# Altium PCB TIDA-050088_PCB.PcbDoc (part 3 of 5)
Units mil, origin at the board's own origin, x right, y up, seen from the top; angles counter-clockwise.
Board outline 8500 x 7000 mil, 8 copper layers (Top Layer, Layer 1 - GND, Signal Layer 2, Layer 3 - GND, Layer 4 - Power, Signal Layer 5, Layer 6 - GND, Bottom Layer), stack 61.6 mil thick; 537 components, 169 nets, 1427 pads, 1411 vias.
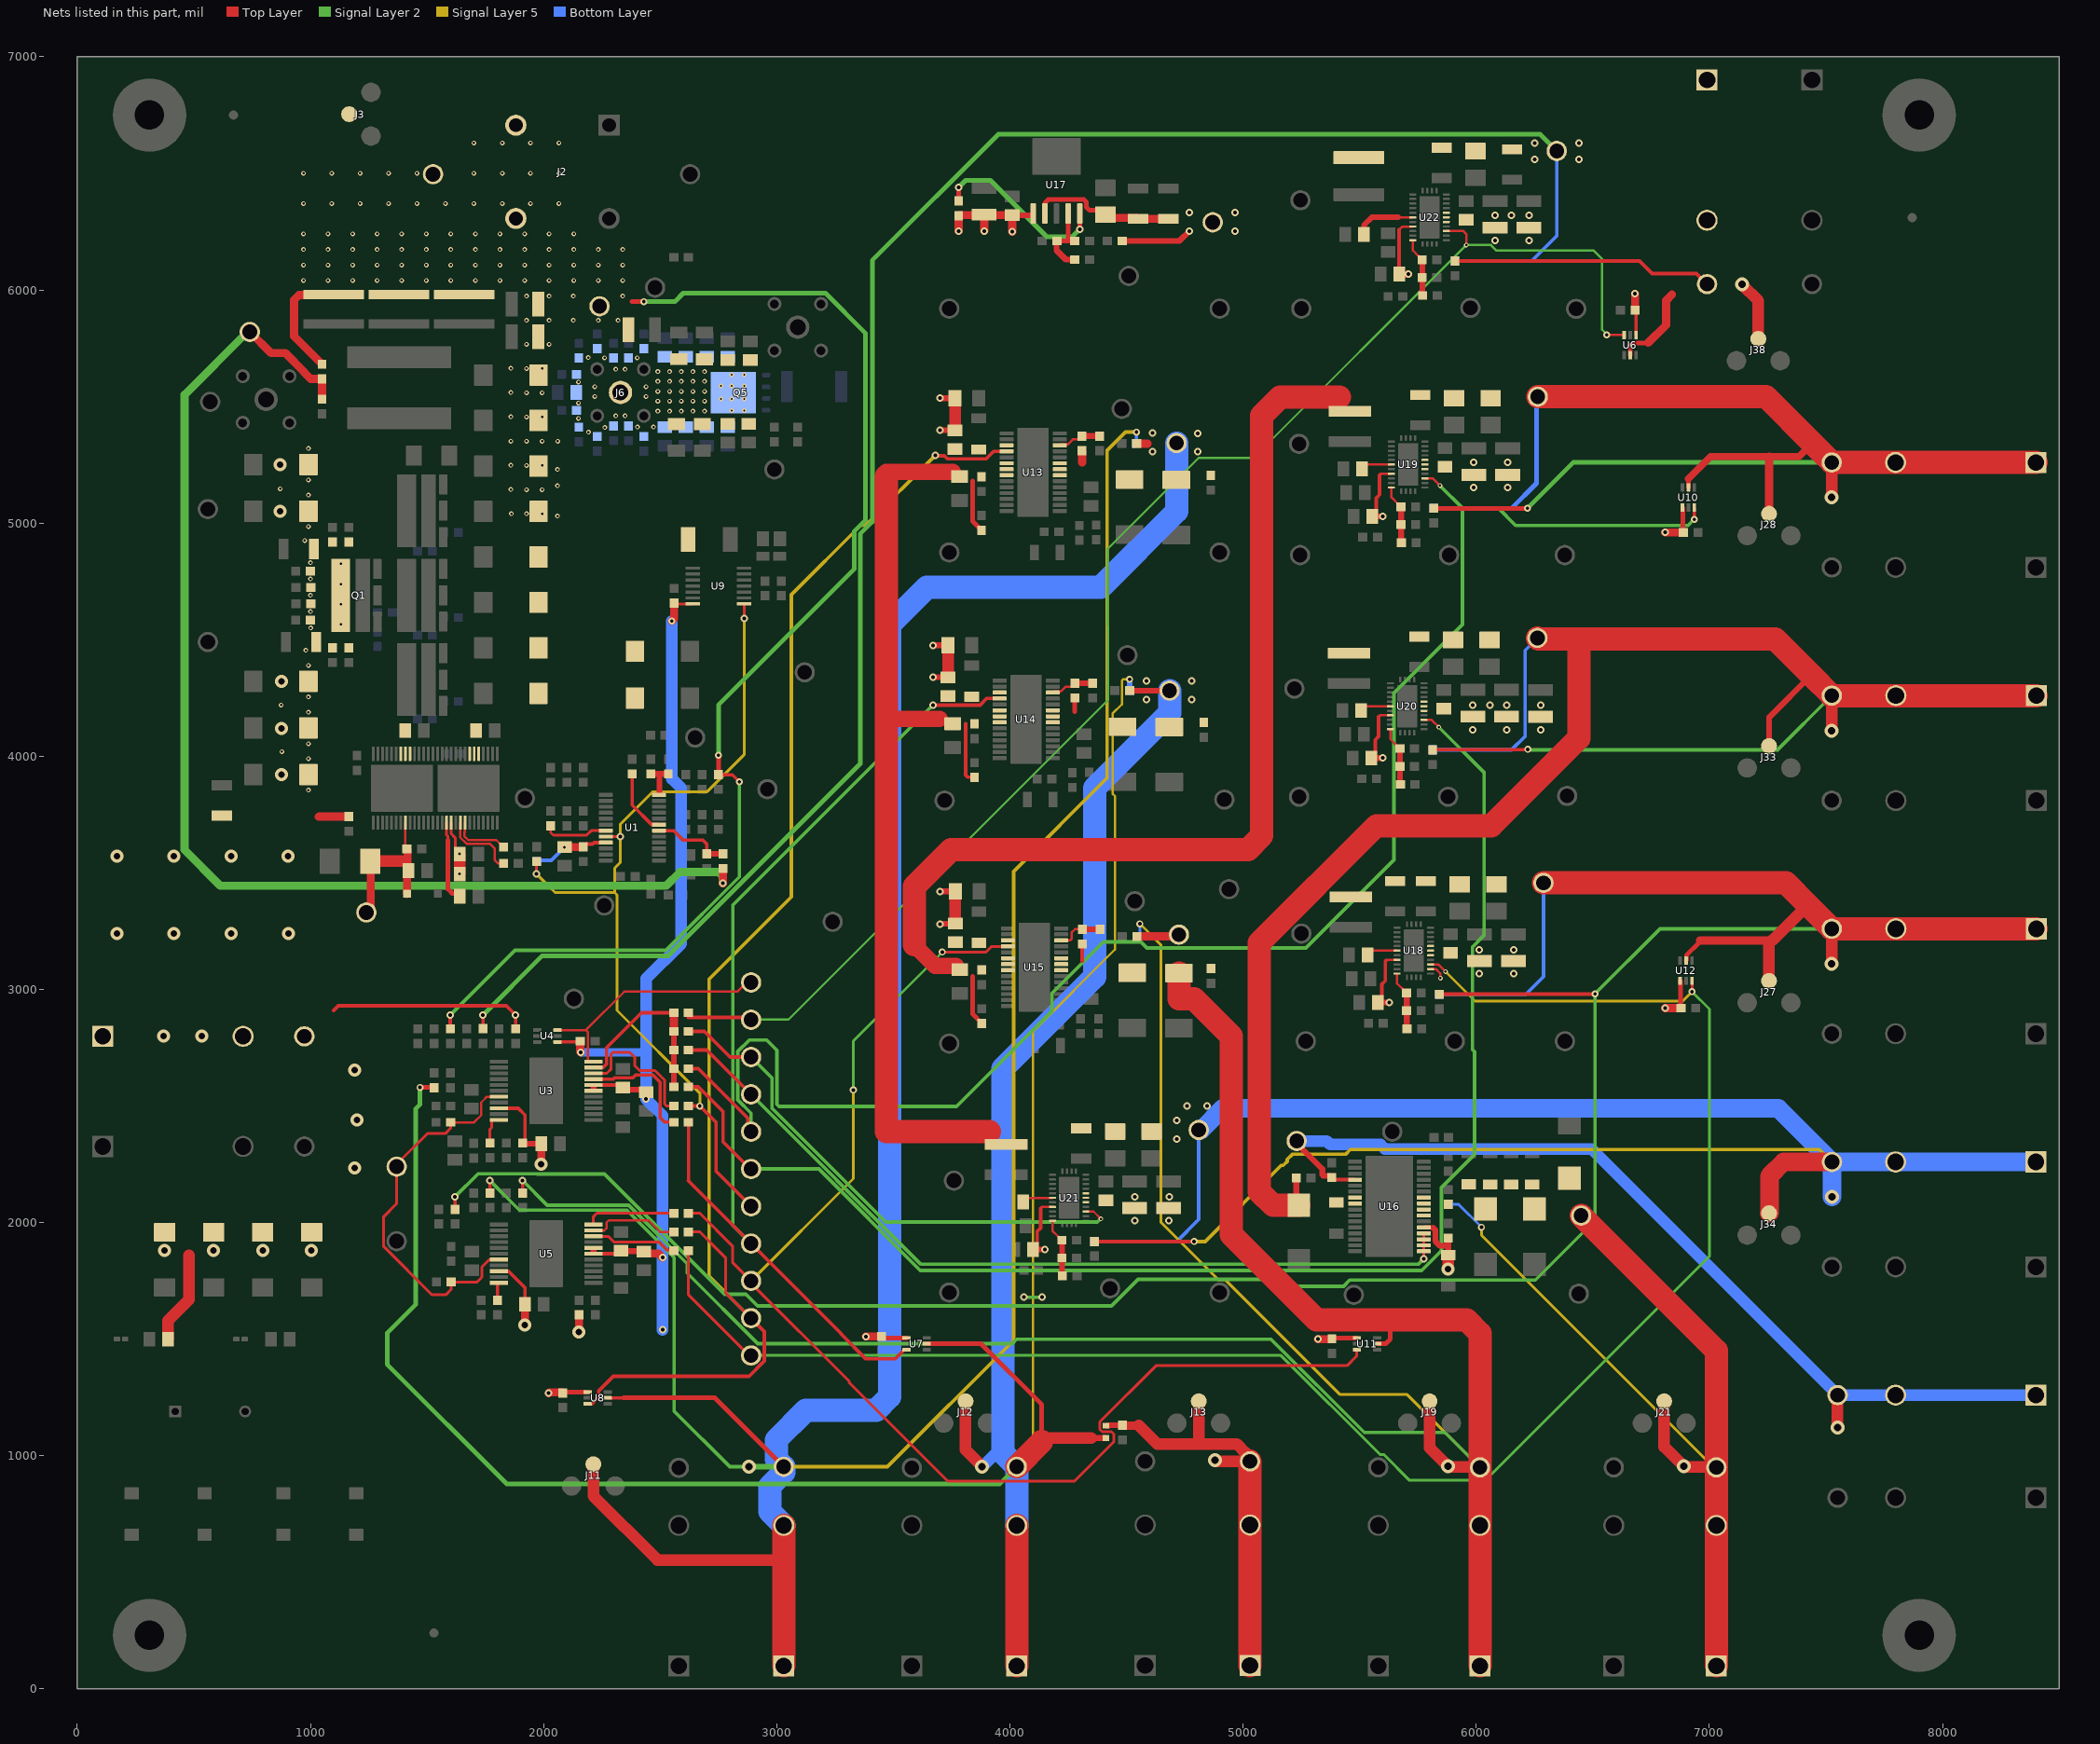
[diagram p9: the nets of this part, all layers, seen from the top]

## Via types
v1: diameter 20, hole 10, Top Layer to Bottom Layer, 671 vias
v2: diameter 32, hole 16, Top Layer to Bottom Layer, tented both sides, 369 vias
v3: diameter 19.68, hole 7.87, Top Layer to Bottom Layer, 176 vias
v4: diameter 19.68, hole 7.87, Top Layer to Bottom Layer, tented both sides, 60 vias
v5: diameter 32, hole 16, Top Layer to Bottom Layer, 30 vias
v6: diameter 56, hole 28, Top Layer to Bottom Layer, 26 vias
v7: diameter 30, hole 15, Top Layer to Bottom Layer, 24 vias
v8: diameter 60, hole 32, Top Layer to Bottom Layer, 22 vias
v9: diameter 20, hole 10, Top Layer to Bottom Layer, tented both sides, 15 vias
v10: diameter 31.5, hole 19.68, Top Layer to Bottom Layer, 10 vias
v11: diameter 24, hole 12, Top Layer to Bottom Layer, 6 vias
v12: diameter 20, hole 8, Top Layer to Bottom Layer, tented both sides, 1 vias
v13: diameter 28, hole 14, Top Layer to Bottom Layer, 1 vias

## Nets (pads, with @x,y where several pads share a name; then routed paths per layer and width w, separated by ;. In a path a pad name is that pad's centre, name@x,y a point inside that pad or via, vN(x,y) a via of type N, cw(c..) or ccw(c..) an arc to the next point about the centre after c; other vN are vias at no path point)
0V6_VTT: C125.1 C126.1 C127.1 C128.1 C129.1 C130.1 C131.1 J18.1 J18.2 J21.1 R98.1 R99.1 TP50.1 TP51.1 U16.23 U16.24 U16.25 U16.26 | length 4265.1
  Top Layer w50: J21.1@6806.3,1234 6806.3,1038.24 v8(6890,954.53) 6891.91,952.62 7027.38,952.62 TP51.1@7030,950
  Top Layer w100: TP50.1@6450,2030 7030,1450 TP51.1@7030,950 J18.2@7030,701.18 J18.1@7030,98.82
  Signal Layer 5 w12: v7(6022.6,1980) 6022.6,1945.47 7018.07,950 TP51.1@7030,950
  Bottom Layer w12: R99.1@5880,2078.5 5924.09,2078.5 v7(6022.6,1980)
0V6_VTTREF: C134.1 J20.1 J20.2 TP53.1 TP54.1 U16.4 | length 4102.4
  Top Layer w15: C134.1@5380,2193.5 5389.54,2183.97 U16.4@5479.91,2183.97
  Top Layer w25: TP53.1@5230,2350 5230,2340 5340,2230 5340,2205 5344.31,2200.69 5373.8,2200.69 5380,2194.49 C134.1@5380,2193.5
  Top Layer w50: v8(7550,1120) TP54.1@7550,1260
  Bottom Layer w50: TP53.1@5230,2350 5358.5,2350 5373.5,2335 5589.64,2335 5609.14,2315.5 6494.5,2315.5 TP54.1@7550,1260 J20.2@7798.82,1260 J20.1@8401.18,1260
0V8: C32.2 C33.2 C34.2 C35.2 C36.2 C37.2 C38.2 C39.2 C40.2 C41.2 C42.1 C48.1 C49.1 C50.1 C51.1 C52.1 C53.1 C54.1 C55.1 C56.1 C57.1 C58.1 C59.1 C60.1 C61.1 C62.1 C63.1 C64.1 C65.1 C66.1 C67.1 C68.1 C69.1 C70.1 C71.1 C72.1 C73.1 C74.1 C75.1 C76.1 C77.1 C78.1 C79.1 J2.2 J3.1 J6.1 Q5.5 Q5.6 Q5.7 Q5.8 Q5.9@2814.06,5560 R1.2 R23.2 R25.2 R27.2 R48.2 R76.2 TP6.1 TP7.1 | length 5800.6
  Top Layer w15: R48.2@1600,2831.07 v5(1600,2890) ; R1.2@2750,3921.54 2751.53,3920 2810,3920 v7(2840,3890)
  Top Layer w20: 2380,5950 v7(2430,5950) ; R1.2@2750,3921.54 v7(2750,4003.87)
  Top Layer w35: C42.1@1050,5681.5 1050,5682.48 1048.8,5683.68 1047.82,5683.68 930,5801.5 930,5957.49 950.5,5977.99 1097.81,5977.99 R27.2@1100,5980.18
  Signal Layer 2 w15: v5(1600,2890) 1877.71,3167.71 2525.23,3167.71 2840,3482.48 v7(2840,3890)
  Signal Layer 2 w20: v7@2430,5950.5 2563.73,5950.5 2599.23,5986 3209.05,5986 3380,5815.05 3380,5012.02 3332,4964.02 3332,4802 2750,4220 v7(2750,4003.87)
  other v1: 2060,5030 1861.36,5039.94 1927,5039.94 1994,5039.94 1860,5144.24 1927,5143.51 1994,5143.51 2060,5160 2060,5230 1927,5247.09 1994,5247.09 1860,5247.82 1860,5351.39 1927,5350.67 1994,5350.67 2061,5350.67 2192.73,5390 2262.73,5410 2402.73,5411.5 2471.36,5411.5 2150,5449.1 1927,5454.97 1994,5454.97 1860,5455.7 2310,5460 2350,5460 2490,5480 2540,5480 2590,5480 2640,5480 2690,5480 2150,5515.32 2490,5522.5 2540,5522.5 2590,5522.5 2640,5522.5 2690,5522.5 2220,5542.5 2440,5542.5 1927,5559.27 1994,5559.27 1860,5560 2490,5565 2540,5565 2590,5565 2640,5565 2690,5565 2220,5585 2440,5585 2150,5604.55 2490,5607.5 2540,5607.5 2590,5607.5 2640,5607.5 2690,5607.5 2490,5650 2540,5650 2590,5650 2640,5650 2690,5650 2310,5660 2350,5660 1927,5662.85 1994,5662.85 1860,5663.58 2261.36,5708.5 2401.36,5708.5 2191.36,5710 1927,5766.4 2023.84,5766.42 1927,5870 2023.84,5870 2128,5870 2234.61,5870 2320,5869.97 1927,5973.58 2023.84,5973.58 2128,5973.58 2340,5973.58 970,6040.24 1075.38,6040.24 1180.77,6040.24 1286.15,6040.24 1391.54,6040.24 1496.92,6040.24 1602.31,6040.24 1707.69,6040.24 1813.08,6040.24 1918.46,6040.24 2023.84,6040.24 2129.23,6040.24 2234.61,6040.24 2340,6040.24 970,6106.91 1075.38,6106.91 1180.77,6106.91 1286.15,6106.91 1391.54,6106.91 1496.92,6106.91 1602.31,6106.91 1707.69,6106.91 1813.08,6106.91 1918.46,6106.91 2023.84,6106.91 2129.23,6106.91 2234.61,6106.91 2340,6106.91 970,6173.58 1075.38,6173.58 1180.77,6173.58 1286.15,6173.58 1391.54,6173.58 1496.92,6173.58 1602.31,6173.58 1707.69,6173.58 1813.08,6173.58 1918.46,6173.58 2023.84,6173.58 2129.23,6173.58 2234.61,6173.58 2340,6173.58 970,6240.24 1075.38,6240.24 1180.77,6240.24 1286.15,6240.24 1391.54,6240.24 1496.92,6240.24 1602.31,6240.24 1707.69,6240.24 1813.08,6240.24 1918.46,6240.24 2023.84,6240.24 2129.23,6240.24 970,6370.24 1091.78,6370.24 1213.56,6370.24 1335.33,6370.24 1457.11,6370.24 1578.89,6370.24 1700.67,6370.24 1822.44,6370.24 1944.22,6370.24 2066,6370.24 970,6500.24 1091.78,6500.24 1213.56,6500.24 1335.33,6500.24 1457.11,6500.24 1700.67,6500.24 1822.44,6500.24 1944.22,6500.24 2066,6500.24 1700.67,6630.24 1822.44,6630.24 1944.22,6630.24 2066,6630.24
  other v3: 2807.6,5482.83 2860.35,5482.83 2760.75,5531.85 2807.6,5531.85 2860.35,5531.85 2760.75,5588.15 2807.6,5588.15 2860.35,5588.15 2807.6,5637.17 2860.35,5637.17
0V92: C118.2 C119.2 C121.1 J17.1 J17.2 J19.1 R62.2 R100.2 R101.2 R104.2 TP48.1 TP49.1 U11.5 U15.21 U15.22 U15.23 | length 12690.8
  Top Layer w12: R101.2@4544.73,3226.29 4545.94,3227.49 R101.2@4557.44,3238.99
  Top Layer w15: R62.2@1910,2127.05 v5(1910,2180) ; 4310.32,3120.32 R104.2@4310.32,3194.79
  Top Layer w20: U11.5@5574.78,1480 5611.57,1480 5631.57,1500 5631.57,1563.74 5650.18,1582.35
  Top Layer w35: R101.2@4545.94,3227.49 4717.49,3227.49 TP48.1@4725,3235
  Top Layer w50: J19.1@5800,1234 5800,1034.53 v8(5880,954.53) 5881.91,952.62 6013.5,952.62 TP49.1@6016.12,950
  Top Layer w100: C119.2@4725.1,3069.98 4725,3069.88 4725,2960 4790,2960 4950,2800 4950,1948.28 5315.94,1582.35 5650.18,1582.35 5958.68,1582.35 6016.12,1524.91 TP49.1@6016.12,950 J17.2@6016.12,701.18 J17.1@6016.12,98.82
  Signal Layer 2 w15: v5(1910,2180) 2015.63,2074.37 2365.32,2074.37 2615.86,1823.84 2615.86,1783.53 2918.89,1480.5 4009.7,1480.5 4029.2,1500 5120,1500 5520,1100 5866.12,1100 TP49.1@6016.12,950
  Signal Layer 5 w12: v7(4557.44,3281.34) 4648,3190.78 4648,2001.2 4893.7,1755.5 4922.99,1755.5 5416.49,1262 5704.12,1262 TP49.1@6016.12,950
  Bottom Layer w12: R100.2@4544.73,3226.29 4557.44,3238.99 v7(4557.44,3281.34)
1V2: C153.1 C154.1 C155.1 C156.1 J25.1 J25.2 J27.1 L2.2 R66.2 R117.2 R118.2 TP66.1 TP67.1 U12.5 | length 12191.7
  Top Layer w15: R66.2@1620,2057.05 v5(1620,2110) ; R117.2@5842.01,2978.78 5843.27,2980.03 6508.75,2980.03 v7(6510,2981.28)
  Top Layer w20: U12.5@6900,3123.31 6901.72,3125.02 6901.72,3146.5 6955.22,3200
  Top Layer w35: 6960,3210 7256,3210 7280,3210
  Top Layer w50: J27.1@7256,3036.69 7256,3200 ; 7270,3210 7422.55,3362.55 ; v8(7524.83,3110) 7524.96,3110.13 7524.96,3259.87 TP67.1@7525.09,3260
  Top Layer w100: TP66.1@6288.47,3457.01 7328.08,3457.01 7422.55,3362.55 TP67.1@7525.09,3260 J25.2@7800,3260 J25.1@8402.36,3260
  Signal Layer 2 w15: v5(1620,2110) 1719.5,2209.5 1971.81,2209.5 1972.81,2208.5 2260.9,2208.5 2776.4,1693 2867.61,1693 2917.61,1643 4435.35,1643 4549.35,1757 5138.39,1757 5168.89,1726.5 5430.89,1726.5 5457.89,1753.5 6254.11,1753.5 6510,2009.39 v7(6510,2981.28) 6788.72,3260 TP67.1@7525.09,3260
  Bottom Layer w15: R118.2@5842.01,2978.78 6212.46,2978.78 6288.47,3054.79 TP66.1@6288.47,3457.01
1V2_MEM: C132.1 C133.1 C175.1 C176.1 C177.1 J31.1 J31.2 J33.1 L4.2 R103.1 R127.2 R128.2 TP82.1 TP83.1 U16.7 U16.8 | length 8988.9
  Top Layer w15: R127.2@5813.38,4027.23 5814.63,4028.48 6219.78,4028.48 v7(6221.04,4029.73)
  Top Layer w25: R103.1@5228.5,2191.77 5228.5,2085.59 C132.1@5240,2074.09 ; J33.1@7256.3,4043.9 7256.3,4166.3 7437.55,4347.55
  Top Layer w50: v8(7524.83,4110) 7524.96,4110.13 7524.96,4259.87 TP83.1@7525.09,4260
  Top Layer w100: C132.1@5240,2074.09 5239.8,2073.9 5128.58,2073.9 5070,2132.48 5070,3199.99 5572.32,3702.32 6064.85,3702.32 6440,4077.47 6440,4503.43 ; TP82.1@6262.44,4507.19 6266.2,4503.43 6440,4503.43 ; J31.1@8402.36,4260 J31.2@7800,4260 TP83.1@7525.09,4260 7437.55,4347.55 7281.66,4503.43 6440,4503.43
  Signal Layer 2 w15: v7(6221.04,4029.73) 6223.54,4027.23 7292.32,4027.23 TP83.1@7525.09,4260
  Bottom Layer w15: R128.2@5813.38,4027.23 6151.21,4027.23 6209.5,4085.51 6209.5,4454.24 TP82.1@6262.44,4507.19
1V2_VCCO: C122.1 C123.1 C157.1 C158.1 C159.1 J26.1 J26.2 J28.1 L3.2 R102.2 R119.2 R120.2 TP68.1 TP69.1 U10.5 U15.6 U15.7 U15.8 | length 10391.6
  Top Layer w20: 3840,3056.77 3840,2894.47 3879.4,2855.06 R102.2@3879.4,2854.08 ; R119.2@5817.73,5063.68 v7(6220,5063.68) ; U10.5@6910,5153.31 6910,5190
  Top Layer w30: 6910,5190 7005,5285 7256,5285 7385,5285 7442.5,5342.5 ; 7460,5285 7480,5305
  Top Layer w35: J28.1@7256,5040 7256,5285
  Top Layer w50: TP69.1@7525,5260 TP69.1@7525,5260 7525.05,5110.05 v8(7525.09,5110)
  Top Layer w70: 3590,3191.26 3680,3100 C122.1@3768.74,3100
  Top Layer w100: 3590,3191.26 3590,3441.42 3748.58,3600 5021.42,3600 5080,3658.58 5080,5460 5160,5540 5413.87,5540 ; TP68.1@6264.18,5541.92 7243.08,5541.92 7442.5,5342.5 7480,5305 TP69.1@7525,5260 J26.2@7798.82,5260 J26.1@8401.18,5260
  Signal Layer 2 w20: v7(6220,5063.68) 6416.32,5260 TP69.1@7525,5260
  Bottom Layer w20: R120.2@5817.73,5063.68 6152.21,5063.68 6258.95,5170.42 6258.95,5536.68 TP68.1@6264.18,5541.92
1V5: C101.2 C102.2 C106.1 FB1.1 J9.1 J9.2 J12.1 R49.2 R81.2 R82.2 R86.2 TP35.1 TP36.1 U7.5 U14.21 U14.22 U14.23 | length 14256.6
  Top Layer w10: v7@4513.31,4329.69 v7(4513.62,4330)
  Top Layer w20: v7(1470,2580) 1470.75,2579.25 1529.25,2579.25 R49.2@1530,2578.5 ; U7.5@3643.31,1480 3876.26,1480 4136.69,1219.57 4136.69,1060.03 ; 4278.89,4191.11 R86.2@4278.89,4250.04 R86.2@4280,4248.93
  Top Layer w25: 4136.69,1060.03 4152.61,1075.95 ; 4348.56,1075.95 FB1.1@4411.77,1075.95 ; R82.2@4513.31,4281.54 TP35.1@4685,4281.54
  Top Layer w50: J12.1@3810,1234 3810,1025 3879.48,955.52 v8(3879.48,952.82) ; 4152.61,1075.95 4348.56,1075.95
  Top Layer w100: J9.1@4029.48,98.82 J9.2@4029.48,701.18 ; TP36.1@4029.48,952.82 4136.69,1060.03
  Signal Layer 2 w20: v7(1470,2580) 1470,2506.85 1452,2488.85 1452,1649.08 1329,1526.08 1329,1392.18 1841.18,880 3956.66,880 TP36.1@4029.48,952.82
  Signal Layer 5 w10: TP36.1@4029.48,952.82 4100,1023.34 4100,2820.3 4451,3171.3 4451,3828.7 4440.31,3839.39 4440.31,4182.57 4480,4222.25 4480,4324.14 4485.86,4330 v7(4513.62,4330)
  Bottom Layer w25: R81.2@4513.31,4281.54 4513.46,4281.69 4513.46,4329.84 v7(4513.62,4330)
  Bottom Layer w50: v8@3879.48,957.82 v8@3882.19,957.82 ; v8@3882.19,952.82 3942.19,1012.82 3969.48,1012.82
  Bottom Layer w100: J9.2@4029.48,701.18 TP36.1@4029.48,952.82 3969.48,1012.82 3969.48,2659.48 4363.17,3053.17 4363.17,3863.17 4685,4185 TP35.1@4685,4281.54
  other v2: 4586.07,4243.97 4780.43,4243.97 4780.43,4322.38 4586.07,4323.36
1V5_GTY: C99.2 C100.2 C103.1 J8.1 J8.2 J11.1 R64.2 R79.2 R80.2 R85.2 TP33.1 TP34.1 U8.5 U13.21 U13.22 U13.23 | length 16288.2
  Top Layer w15: R64.2@1770,2127.05 v5(1770,2180) ; U8.5@2275.3,1248.02 2342.64,1248.02
  Top Layer w20: 2342.64,1248.02 2734.8,1248.02 TP34.1@3030,952.82
  Top Layer w35: R85.2@4308.89,5310.04 4310,5308.93 4310,5260 ; R80.2@4543.31,5341.54 4544.51,5340.34 4589.66,5340.34 4590,5340
  Top Layer w50: J11.1@2213.7,963.9 2213.7,827.34 2488.04,553 3013,553 3030,570
  Top Layer w100: J8.1@3030,98.82 3030,570 J8.2@3030,701.18
  Signal Layer 2 w15: v5(1770,2180) 1896.63,2053.37 2356.63,2053.37 2560,1850 2560,1191.3 2798.48,952.82 v8(2880,952.82)
  Signal Layer 2 w25: v8(2880,952.82) TP34.1@3030,952.82
  Signal Layer 5 w15: TP34.1@3030,952.82 3474.54,952.82 4015.69,1493.97 4015.69,3505.69 4416.5,3906.5 4416.5,5310.96 4495.54,5390 v7(4543.31,5390)
  Bottom Layer w15: R79.2@4543.31,5341.54 v7(4543.31,5390)
  Bottom Layer w100: J8.2@3030,701.18 2970,761.18 2970,868.59 3030,928.59 TP34.1@3030,952.82 2997.83,984.99 2997.83,1067.83 3125,1195 3426.42,1195 3485,1253.58 3485,4565 3645,4725 4390,4725 4715,5050 TP33.1@4715,5343.36
  other v2: 4611.07,5306.52 4805.43,5306.52 4805.43,5384.93 4611.07,5385.91
1V5_SMON: C109.1 FB1.2 J10.1 J10.2 J13.1 TP37.1 | length 1908
  Top Layer w25: FB1.2@4411.77,1129.1 4412.75,1129.1 4413.05,1129.39 4424.76,1129.39 4426.11,1130.75 4476.11,1130.75 4476.43,1131.06 C109.1@4482.31,1131.06
  Top Layer w35: C109.1@4482.31,1131.06 4482.31,1130.39 4483.52,1129.19 4553.52,1129.19
  Top Layer w50: 4553.52,1129.19 4632.7,1050 4810,1050 ; J13.1@4810,1234 4810,1050 ; v8@4881.91,978.62 v8(4880,980.53) 4882.71,980.53 4887.24,976 TP37.1@5030,976 5030,986.01 5010,1006.01 5010,1013.34 4973.34,1050 4810,1050
  Top Layer w100: J10.1@5030,100.45 J10.2@5030,702.81 TP37.1@5030,976
2V5_DDR: C104.1 C105.1 C107.1 C108.1 C178.1 C179.1 C180.1 J32.1 J32.2 J34.1 L5.2 R83.2 R84.2 R129.2 R130.2 TP80.1 TP81.1 U13.6 U13.7 U13.8 U14.6 U14.7 U14.8 | length 12858.3
  Top Layer w15: 3810,4140 3810,3918.79 3818.79,3910 3847.3,3910 R84.2@3847.98,3909.33 ; R129.2@4363.58,1918.89 v7(4790,1918.89)
  Top Layer w20: 3840,5180 3840,5008.29 3877.98,4970.31 R83.2@3877.98,4969.33
  Top Layer w50: C107.1@3746.6,4139.51 C107.1@3754.47,4139.51 ; C104.1@3756.11,5220 3776.6,5199.51 C104.1@3784.47,5199.51
  Top Layer w70: 3470,4160 3698.33,4160 ; 3470,5220 C104.1@3756.11,5220
  Top Layer w80: J34.1@7256,2040 7257.44,2041.44 7257.44,2199.21 7318.23,2260 TP80.1@7525.63,2260
  Top Layer w100: 3470,5200 3470,4160 3470,2390 3912.18,2390
  Signal Layer 5 w15: v7(4790,1918.89) 4837.17,1918.89 5163.67,2245.39 5172.22,2245.39 5189.5,2262.67 5189.5,2271.22 5211.05,2292.77 5439.53,2292.77 5460.27,2313.5 7472.13,2313.5 TP80.1@7525.63,2260
  Bottom Layer w15: R130.2@4363.58,1918.89 4715.17,1918.89 4810.04,2013.76 TP81.1@4810.04,2397.13
  Bottom Layer w50: TP81.1@4810.04,2397.13 TP81.1@4820.05,2397.13
  Bottom Layer w80: TP81.1@4813.28,2397.13 4813.28,2398.47 4821.39,2398.47 4912.93,2490 7295.63,2490 TP80.1@7525.63,2260 ; v8(7525.63,2110) TP80.1@7525.63,2260 ; J32.1@8401.18,2260 J32.2@7798.82,2260 TP80.1@7525.63,2260
  other v2: 4716.28,2358.18 4716.28,2437.58 4760,2500 4845,2500
3V3_VCCO: C111.1 C115.1 C124.1 C136.1 C164.1 C165.1 C185.1 C186.1 C191.1 C192.1 C193.1 C196.1 J37.1 J37.2 J38.1 L6.2 R46.2 R87.1 R88.1 R105.1 R106.2 R137.2 R138.2 TP94.1 TP95.1 U6.5 U16.21 U18.8 U18.17 U19.8 U20.8 U21.8 U22.8 | length 12779.3
  Top Layer w10: 4137.96,2066.97 U21.8@4182.44,2066.97 ; 5587.75,4175.31 U20.8@5632.23,4175.31 ; 5592.1,5211.76 U19.8@5636.58,5211.76 ; 5616.39,3126.86 U18.8@5660.87,3126.86 ; 5669.65,6258.11 5683.52,6271.98 U22.8@5728,6271.98 ; U18.17@5804.57,3087.49 5804.65,3087.41 5826.68,3087.41 5845.3,3068.78 5845.3,3049.24 v9(5846.59,3047.95)
  Top Layer w15: R46.2@1740,2831.5 v5(1740,2890) ; C186.1@4108.23,1884.04 4117.07,1892.89 4117.07,1962.15 4131.59,1976.67 4131.59,2060.6 4134.43,2063.44 ; C185.1@5558.02,3992.38 5566.86,4001.23 5566.86,4070.48 5581.39,4085.01 5581.39,4168.94 5584.23,4171.78 ; C165.1@5562.37,5028.84 5571.21,5037.68 5571.21,5106.94 5585.74,5121.46 5585.74,5205.39 5588.57,5208.23 ; C164.1@5586.66,2943.93 5595.5,2952.78 5595.5,3022.03 5610.02,3036.56 5610.02,3120.49 5612.86,3123.33 ; C196.1@5669.65,6067.7 5669.65,6258.11 ; U16.21@5775.19,1979.24 U16.21@5775.95,1980 ; R137.2@5909.14,6123.89 6700.56,6123.89 6754.45,6070 6945,6070 TP95.1@6990,6025
  Top Layer w18: U16.21@5775,1979 5815,1979
  Top Layer w20: U6.5@6660,5719.93 6660,5761.11 6671.72,5772.83 6737.83,5772.83
  Top Layer w25: v2(3670,4340) 3670.94,4339.06 3733.48,4339.06 R88.1@3734.42,4338.11 ; v2(3670,4475.74) C115.1@3734.42,4475.74 ; v2(3700,3280) 3701.34,3281.34 3764.33,3281.34 R105.1@3765.85,3282.86 ; v2(3700,3420) 3700.24,3420.24 3765.61,3420.24 C136.1@3765.85,3420.49 ; v2(3700,5398.11) R87.1@3764.62,5398.11 ; v2(3700,5535.74) C111.1@3764.42,5535.74 C111.1@3764.62,5535.74 ; C186.1@4099.57,1884.04 4108.23,1884.04 v2(4150,1884.04) ; C185.1@5549.36,3992.38 5558.02,3992.38 v2(5600,3992.38) ; C165.1@5553.71,5028.84 5562.37,5028.84 v2(5600,5028.84) ; C164.1@5578,2943.93 5586.66,2943.93 v2(5627.55,2943.93) ; 5815,1977.25 5825,1967.25 5825,1920 5845,1900 5880,1900 ; C124.1@5880,1860.94 5880,1900 ; R106.2@5880,1933.39 5880,1900
  Top Layer w30: C196.1@5669.65,6067.7 v2(5710,6067.7)
  Top Layer w35: 6737.83,5772.83 6815,5850 6815,5955 6840,5980
  Top Layer w50: R88.1@3734.42,4338.11 C115.1@3734.42,4475.74 ; R87.1@3764.62,5398.11 C111.1@3764.62,5535.74 ; R105.1@3765.85,3282.86 C136.1@3765.85,3420.49 ; v6(5880,1800) C124.1@5880,1860.94 ; v8(7141.3,6025) 7141.3,6022.29 7210,5953.59 J38.1@7210,5790
  Signal Layer 2 w15: v2(4059.57,1680) v2(4137.96,1680)
  Signal Layer 2 w20: v5(1740,2890) 1994.21,3144.21 2534.96,3144.21 3358,3967.24 3358,4953.25 3410,5005.25 3410,6126.77 3950.02,6666.79 6274.67,6666.79 TP94.1@6345.6,6595.86
  Bottom Layer w15: R138.2@5909.14,6123.89 6237.92,6123.89 6345.6,6231.57 TP94.1@6345.6,6595.86
  other v2: 6250,6560 6440,6560 6250,6630 6440,6630
5V0_SYS: C81.1 C82.1 C84.1 C88.1 C89.1 C92.1 C93.1 C94.1 C95.1 C96.1 C97.1 C98.1 C141.1 C142.1 C143.1 R112.2 TP62.1 U3.17 U3.18 U4.1 U5.17 U5.18 U6.1 U7.1 U8.1 U9.14 U10.1 U11.1 U12.1 U17.2 | length 6325.6
  Top Layer w12: C95.1@2563.48,4653.23 U9.14@2637.8,4653.23
  Top Layer w15: U4.1@2059.75,2774.41 2060.12,2774.78 C84.1@2154.6,2774.78 ; U5.17@2213.87,1866.24 2318.24,1866.24 C88.1@2331.99,1880 ; U3.18@2214,2590 2330,2590 C81.1@2340,2580 ; C92.1@6681.5,5913.24 6685.22,5909.52 6685.22,5806.92 U6.1@6685.59,5806.54
  Top Layer w20: C94.1@2084.37,1271.89 2186.97,1271.89 U8.1@2188.69,1273.61 ; C93.1@3448.8,1510 3453.21,1505.59 U7.1@3556.69,1505.59 ; U17.2@4150,6327.95 4150,6372.91 4164.35,6387.26 4317.26,6387.26 4327.81,6376.71 4327.81,6354.81 4341.5,6341.13 4391.39,6341.13 C143.1@4410,6322.52 ; C97.1@5381.47,1501.5 5385.56,1505.59 U11.1@5488.16,1505.59 ; U12.1@6874.41,3036.69 6876.13,3034.98 C98.1@6876.13,2922.38 ; C96.1@6886.13,4962.38 U10.1@6886.13,5064.98
  Top Layer w25: U5.17@2213.87,1871.24 U5.18@2213.87,1886.24 ; U3.17@2214,2570 U3.18@2214,2582.26 ; C88.1@2331.99,1880 2334.62,1877.37 2427.37,1877.37 C89.1@2430,1874.75 ; C81.1@2340,2580 2350,2570 2430,2570 C82.1@2440,2560 v5(2440,2530) ; R112.2@4481.5,6210 4727.45,6210 v2(4770.42,6252.97)
  Top Layer w35: v5(2021.99,1268.02) 2025.87,1271.89 C94.1@2084.37,1271.89 ; C84.1@2154.6,2774.78 2157.3,2772.09 2157.3,2732.7 v5(2160,2730) ; C89.1@2430,1874.75 2437.5,1867.25 2492.75,1867.25 v5(2510,1850) ; v7(2550,4580) 2559.7,4589.7 C95.1@2559.7,4657.01 ; v5(3382.34,1511.5) 3448.8,1511.5 C93.1@3448.8,1510 ; C143.1@4410,6322.52 4423.33,6309.19 4545.85,6309.19 C141.1@4550,6305.04 C142.1@4680,6305.04 ; v5(5321.47,1500) 5380.27,1500 5381.47,1501.2 C97.1@5381.47,1501.5 ; C92.1@6681.5,5913.24 v5(6681.5,5983.24) ; v5(6810,2920) 6873.75,2920 C98.1@6876.13,2922.38 ; v5(6810,4960) 6883.75,4960 C96.1@6886.13,4962.38
  Bottom Layer w35: v5(2160,2730) 2440,2730
  Bottom Layer w50: v5(2510,1540) v5(2510,1850) 2510,2460 v5(2440,2530) 2440,2730 2440,3045.99 2590,3195.99 2590,3863 2550,3902.99 v7(2550,4580)
  other v2: 4964.78,6252.97 4964.78,6331.38 4770.42,6332.37
12V0_SYS: C1.2 C2.2 C3.2 C4.2 C5.2 C6.1 C7.1 C8.1 C9.1 C10.1 C11.1 C12.1 C13.1 C14.1 C15.1 C16.1 C17.1 C18.1 C26.1 C27.1 C44.2 C45.2 C46.2 C47.2 C80.1 C87.1 C139.1 C140.1 C147.1 C148.1 C149.1 C150.1 C151.1 C152.1 C168.1 C169.1 C170.1 C171.1 C172.1 C173.1 C174.1 C188.1 C189.1 C190.1 J4.1 J4.2 pad.18 Q1.3 R15.1 R18.2 R44.2 R59.2 R74.2 R111.1 R115.2 TP16.1 U1.9 U3.9 U5.9 U17.1 U18.20 U18.21 U18.22 U19.20 U19.21 U19.22 U20.20 U20.21 U20.22 U21.20 U21.21 U21.22 U22.20 U22.21 U22.22 | length 3280.5
  Top Layer w12: pad.18@1604.07,3715.16 1604.07,3714.55 1603.27,3713.76 1603.27,3668.05 1621,3650.32 1621,3599.84 v11(1640,3580.84) ; U17.1@4094.19,6300 4100,6305.81 U17.1@4100,6327.95
  Top Layer w15: 1100,2910 1120,2930 1840,2930 v5(1880,2890) R44.2@1880,2831.07 ; U5.9@1808.76,1791.24 1809.82,1790.18 1850.69,1790.18 1920,1720.87 C87.1@1920,1650 ; U3.9@1808.88,2490 1890.91,2490 1920,2460.91 1920,2349.6 1910.95,2340.55 R59.2@1910,2341.5 ; C18.1@2181.2,3623.68 2210,3623.68 2216.08,3629.76 U1.9@2266.65,3629.76
  Top Layer w25: R59.2@1916.2,2338.12 C80.1@1989.93,2338.12 ; C140.1@4010,6320 U17.1@4090,6320
  Top Layer w35: 1035,3740 1036.5,3741.5 R15.1@1165.02,3741.5 ; v6(1920,1560) C87.1@1920,1650 ; C80.1@1989.93,2338.12 C80.1@1990,2338.05 v6(1990,2250) ; v11(2090,3610.04) 2090.75,3610.79 2169.25,3610.79 C18.1@2170,3611.54 ; v6(2151.99,1530) R74.2@2151.99,1604.06 ; v2(3780,6252.97) R111.1@3780,6318.5 3780,6319.49 3781.2,6320.69 3887.78,6320.69 3890,6318.47 v2(3890,6252.97) ; C139.1@3891.46,6321.46 4008.54,6321.46 C140.1@4010,6320 v5(4010,6250)
  Top Layer w50: R115.2@390,1500 390,1580 480,1670 480,1860 ; v11(1640,3495) 1640,3574.34 v11(1640,3580.84)
  Bottom Layer w15: R18.2@1970,3548.5 1970,3549.26 1981.2,3560.46 1981.2,3553.5 2033.46,3553.5 v11(2090,3610.04)
  other v1: 991.78,3855 991.78,3990 877.71,4020 991.78,4053.7 991.78,4188.7 874.64,4220 991.78,4255 991.78,4390 980,4455 1001.5,4550 1130,4565.63 1000,4620 1130,4652.09 1000,4690 1130,4738.54 1000,4760 1130,4825 1000,4830 975,4925 991.78,4985 991.78,5120 870,5147.5 991.78,5185 991.78,5320
  other v2: 4535.46,2007.91 4680.88,2007.91 4535.46,2110 4683.43,2110 6013.9,3067.8 6160,3067.8 6013.9,3170 6160,3170 5985.26,4112.48 6131.36,4112.48 6276.09,4112.48 5985.26,4220 6058.7,4220 6131.36,4220 6276.09,4220 5989.61,5152.7 6135.71,5152.7 5989.21,5260 6135.32,5260 6081.02,6212.92 6227.13,6212.92 6081.02,6320 6151.02,6320 6227.13,6320
  other v6: 375,1880 585,1880 795,1880 1004.76,1880 1190.24,2235 1200,2440 1190.24,2655 370,2800 534,2800 170,3240 415,3240 660,3240 905,3240 170,3571.3 414.67,3571.3 659.33,3571.3 904,3571.3 876.35,3921.3 876.35,4120.16 876.35,4321.3 870,5051.3 870,5251.3
BIAS_0V92: C138.1 R105.2 U15.3
BIAS_1V5: C117.1 R88.2 U14.3
BIAS_1V5_GTY: C114.1 R87.2 U13.3
BOOT_0V8: C30.1 C31.1 D1.1 D2.2 pad.8 TP5.1 | length 706
  Top Layer w10: pad.8@1407.22,3715.16 1406.42,3714.37 1406.42,3610.62 C30.1@1414.29,3602.75
  Top Layer w35: TP5.1@1240,3330 1240,3344.07 1258.5,3362.58 1258.5,3548.5 D1.1@1257.01,3550 ; 1390,3550 1406.48,3550 1416.48,3560 ; D2.2@1414.29,3410 1414.29,3504.29 C31.1@1420,3510 1416.48,3513.52 1416.48,3560 ; C30.1@1414.29,3602.75 1415.28,3602.75 1416.48,3601.55 1416.48,3560
  Top Layer w50: D1.1@1257.01,3550 1390,3550
BOOT_1V2: C145.1 U18.6 | length 131.6
  Top Layer w10: C145.1@5534.69,3153.04 5547.88,3166.23 U18.6@5660.87,3166.23
BOOT_1V2_MEM: C166.1 U20.6 | length 131.6
  Top Layer w10: C166.1@5506.06,4201.49 5519.25,4214.68 U20.6@5632.23,4214.68
BOOT_1V2_VCCO: C146.1 U19.6 | length 131.6
  Top Layer w10: C146.1@5510.4,5237.94 5523.59,5251.13 U19.6@5636.58,5251.13
BOOT_2V5_DDR: C167.1 U21.6 | length 131.6
  Top Layer w10: C167.1@4056.26,2093.15 4069.45,2106.34 U21.6@4182.44,2106.34
BOOT_3V3_VCCO: C187.1 U22.6 | length 263.4
  Top Layer w10: 5665.21,6311.35 U22.6@5728,6311.35
  Top Layer w23.62: C187.1@5518.41,6237.67 5518.65,6237.91 5518.65,6277.67 5552.33,6311.35 5665.21,6311.35
BP5H_0V8: C29.1 pad.48 pad.49 pad.50
BP5L_0V8: C43.1 pad.33 pad.34 pad.35
BP7L_0V8: C28.1 pad.17 | length 350.6
  Top Layer w12: pad.17@1584.38,3715.16 1584.38,3714.55 1583.59,3713.75 1583.59,3662.28 1590,3655.87 1590,3640
  Top Layer w20: 1590,3640 1590,3430 1608.5,3411.5 1628.5,3411.5 C28.1@1640,3400
COMP_0V8: C21.1 R7.2 U1.24 | length 156.3
  Top Layer w15: U1.24@2495,3834.49 2495,3838.27 U1.24@2496.73,3840
  Top Layer w25: R7.2@2460,3924.39 C21.1@2535,3924.39 ; U1.24@2496.73,3840 2496.73,3915.07
CS_0V8: C42.2 R6.2 R31.2 TP9.1 | length 5322.9
  Top Layer w35: TP9.1@740,5820 831.08,5728.92 892.51,5728.92 973.64,5647.79 973.64,5645.37 1000.5,5618.5 C42.2@1050,5618.5 R31.2@1050,5531.5 ; v5(2768.68,3455) 2770,3456.32 R6.2@2770,3518.54
  Signal Layer 2 w35: TP9.1@740,5820 730,5820 460,5550 460,3598.47 613.47,3445 2526.37,3445 2584.87,3503.5 2749.11,3503.5 2768.73,3483.88 2768.73,3456.12 2768.68,3456.07 v5(2768.68,3455)
CS_ILIM_0V8: C20.1 R6.1 U1.18 | length 340.9
  Top Layer w15: U1.18@2495,3680.95 2558.17,3680.95 2599.12,3640 2683.68,3640 2700,3623.68 C20.1@2700,3581.54
  Top Layer w25: C20.1@2700,3581.54 R6.1@2770,3581.54
DCL_0V8: R5.2 U1.7 | length 285.1
  Top Layer w10: R5.2@2024.51,3696.61 R5.2@2030,3702.11 2030,3674.04 2041.77,3662.26 2045,3662.26
  Top Layer w12: 2045,3662.26 2185.52,3662.26 2204.2,3680.95 U1.7@2266.65,3680.95
DHL_0V8: pad.20 R26.2 | length 325
  Top Layer w10: pad.20@1643.44,3715.16 1642.64,3714.37 1642.64,3652.04 1669.68,3625 1770,3625 1790,3605 1790,3555 1805,3540 R26.2@1828.5,3540
DLH_0V8: pad.21 R24.2 | length 246.4
  Top Layer w10: pad.21@1663.12,3715.16 1662.33,3714.37 1662.33,3675.01 1661.01,3673.7 1661.01,3656.3 1676.31,3641 1796.52,3641 1827.52,3610 R24.2@1828.5,3610
DLY_SEQ1: R57.2 U3.11 | length 163.7
  Top Layer w12: R57.2@1770,2341.5 1770,2400 1777.44,2407.44 1777.44,2437.44 1780,2440 1837.44,2440 U3.11@1840,2437.44
DLY_SEQ2: R72.2 U5.11 | length 80.3
  Top Layer w15: R72.2@1801.99,1667.05 1801.99,1740.18 1803.06,1741.24 U5.11@1808.76,1741.24
EN1_SEQ2: R61.1 U5.22 | length 384.8
  Top Layer w12: U5.22@2213.87,1991.24 2214,1991.37 2214,2025.55 2228.45,2040 R61.1@2558.5,2040
EN2_SEQ1: R39.1 R40.1 R41.1 R42.1 R43.1 U3.21 | length 800.5
  Top Layer w15: U3.21@2214,2665 2215.06,2666.06 2255.93,2666.06 2270,2680.13 2270,2750 2420,2900 R39.1@2558.5,2900
  Top Layer w25: R42.1@2558.5,2582.26 R40.1@2558.5,2660 R43.1@2558.5,2740 R41.1@2558.5,2820
  Top Layer w35: R41.1@2558.5,2820 R39.1@2558.5,2900
EN2_SEQ2: R63.1 U5.21 | length 397.4
  Top Layer w10: U5.21@2213.87,1966.24 2260,1966.24 2270,1976.24 2270,2000 2280,2010 2450,2010 2500,1960 R63.1@2558.5,1960
EN3_SEQ1: R45.1 U3.20 | length 596
  Top Layer w12: U3.20@2214,2640 2271.37,2640 2290,2658.63 2290,2722.97 2297.03,2730 2370,2730 2390.83,2709.17 2390.83,2673.04 2411.65,2652.21 2477.63,2652.21 2519.5,2610.34 2519.5,2507.76 2527.26,2500 R45.1@2558.5,2500
EN3_SEQ2: R65.1 U5.20 | length 370
  Top Layer w12: U5.20@2213.87,1941.24 2277.28,1941.24 2301.52,1917 2494.24,1917 2527.85,1883.4 2555.11,1883.4 R65.1@2558.5,1880
EN4_SEQ1: R47.1 U3.19 | length 525
  Top Layer w12: R47.1@2556.86,2431.65 R47.1@2558.5,2430
  Top Layer w15: U3.19@2214,2615 2299.41,2615 2305.91,2621.5 2384.03,2621.5 2395.24,2632.71 2469.55,2632.71 2500,2602.26 2500,2450 2518.35,2431.65 R47.1@2556.86,2431.65
EN_0V80: R19.1 R45.2 TP25.1 U1.8 U9.1 | length 3912.2
  Top Layer w12: v5(1970,3495) R19.1@1970,3548.5 ; U1.8@2266.65,3655.36 v5(2330,3655.36) ; 2758.89,2200.61 2889.5,2070 TP25.1@2890,2070 ; v5(2860,4590) 2861.1,4591.1 2861.1,4652.13 U9.1@2862.21,4653.23
  Top Layer w15: R45.2@2622.48,2500 R45.2@2621.5,2500 v7(2670,2500) 2740,2430 2740,2220 TP25.1@2890,2070
  Signal Layer 5 w12: v5(1970,3495) 2049.5,3415.5 2305.12,3415.5 ; v7(2670,2500) 2670,2555.5 2315.5,2910 2315.5,3405.12 2305.12,3415.5 ; v5(2860,4590) 2860,4006.53 2701.38,3847.91 2468.67,3847.91 2330,3709.24 v5(2330,3655.36) 2330,3545.16 2305.12,3520.28 2305.12,3415.5
EN_0V92: R61.2 TP30.1 U11.3 U15.4 | length 5841.7
  Top Layer w12: R61.2@2621.5,2040 2670,2040 2810,1900 2810,1830 TP30.1@2890,1750 2890,1740 3311.44,1318.56 3311.44,1312.76 3733.38,890.82 4277.08,890.82 4445.78,1059.52 4445.78,1092.8 4435.85,1102.74 4395.71,1102.74 4385.99,1112.45 4385.99,1145.74 4626.41,1386.16 5445.78,1386.16 5488.16,1428.54 U11.3@5488.16,1454.41 ; v7(3710,3160) 3897.37,3160 3922.09,3184.72 U15.4@3991.65,3184.72
  Signal Layer 2 w12: v7(3328.52,2568.52) 3328.52,2778.52 v7(3710,3160)
  Signal Layer 5 w12: TP30.1@2890,1750 3328.52,2188.52 v7(3328.52,2568.52)
EN_1V2: R65.2 TP32.1 U12.3 U18.18 | length 7713.5
  Top Layer w10: U18.18@5804.57,3107.17 5837.46,3107.17 v9(5868.68,3075.95) v9@5868.68,3078.66
  Top Layer w12: R65.2@2621.5,1880 2621.5,1690 2881.5,1430 TP32.1@2890,1430 ; v7(6925.59,2990) U12.3@6925.59,3036.69
  Signal Layer 2 w12: TP32.1@2890,1430 5162.42,1430 5586.92,1005.5 5602.99,1005.5 5713.99,894.5 6039.11,894.5 7000,1855.39 7000,2915.59 v7(6925.59,2990)
  Signal Layer 5 w12: v9(5868.68,3075.95) 5994.63,2950 6885.59,2950 v7(6925.59,2990)
EN_1V2_MEM: R42.2 TP22.1 U20.18 | length 6154.8
  Top Layer w10: U20.18@5775.94,4155.62 5808.83,4155.62 v9(5840.04,4124.4) v9@5840.04,4127.11
  Top Layer w15: R42.2@2621.5,2582.26 2663.68,2582.26 2769.95,2475.99 2769.95,2346.19 2886.14,2230 TP22.1@2890,2230
  Signal Layer 2 w15: TP22.1@2890,2230 3180.3,2230 3615.49,1794.81 5766.53,1794.81 5851.46,1879.74 5851.46,2150.72 5993.5,2292.77 5993.5,2732.94 5984.4,2742.05 5984.4,3182.22 6033.5,3231.32 6033.5,3930.95 v9(5840.04,4124.4)
EN_1V2_VCCO: R40.2 TP20.1 U10.3 U19.18 | length 7299
  Top Layer w10: U19.18@5780.28,5192.07 5813.17,5192.07 v9(5844.39,5160.86) v9@5844.39,5163.56
  Top Layer w15: R40.2@2621.5,2660 2663.68,2660 2876.22,2447.46 2876.22,2403.78 TP20.1@2890,2390 ; v7(6935.59,5015.59) U10.3@6935.59,5066.69
  Signal Layer 2 w15: TP20.1@2890,2390 2890,2469.39 2833,2526.39 2833,2733.61 2882.27,2782.88 2957.12,2782.88 3001,2739 3001,2507.18 3009.79,2498.4 3771.63,2498.4 4180.35,2907.12 4180.35,2982.39 4179.98,2982.76 4400.72,3203.5 4561.92,3203.5 4587.42,3178 5269.33,3178 5647.28,3555.95 5647.28,4271.59 5940.79,4565.1 5940.79,5064.46 ; v9(5844.39,5160.86) 5940.79,5064.46 ; v7(6935.59,5015.59) 6933.74,5015.59 6908.15,4990 6169.48,4990 6095.03,5064.46 5940.79,5064.46
EN_1V5: R47.2 TP26.1 U7.3 U14.4 | length 4516.3
  Top Layer w15: R47.2@2621.5,2430 2621.5,2180 2620.75,2179.25 TP26.1@2890,1910 3276.28,1523.73 3276.28,1521.38 3382.34,1415.32 3507.76,1415.32 3546.48,1454.04 3556.32,1454.04 U7.3@3556.69,1454.41 ; v5(3670,4220) 3670.39,4219.61 3872.42,4219.61 3900.59,4247.77 U14.4@3955.76,4247.77
  Signal Layer 2 w15: TP26.1@2890,1910 2812,1988 2812,3362 v5(3670,4220)
EN_1V5_GTY: R63.2 TP31.1 U8.3 U13.4 | length 6079.3
  Top Layer w12: R63.2@2621.5,1960 2670,1960 2780,1850 2780,1700 2784.26,1695.74 TP31.1@2890,1590
  Top Layer w15: U8.3@2188.69,1222.43 2189.06,1222.8 2207,1222.8 2236.59,1252.39 2236.59,1278.43 2299.06,1340.9 2881.51,1340.9 2947,1406.39 2947,1533 TP31.1@2890,1590 ; v5(3680,5290) 3681.36,5288.64 3718.5,5288.64 3731.08,5276.06 3898.87,5276.06 3930.59,5307.77 U13.4@3985.76,5307.77
  Signal Layer 5 w15: TP31.1@2890,1590 2710,1770 2710,3044 3063,3397 3063,4693 3359.87,4989.87 3379.87,4989.87 v5(3680,5290)
EN_2V5_DDR: R41.2 TP21.1 U21.18 | length 2269.2
  Top Layer w10: U21.18@4326.14,2047.28 4359.03,2047.28 v9(4390.25,2016.07) v9@4390.25,2018.77
  Top Layer w15: R41.2@2621.5,2820 2690.03,2820 2800.03,2710 TP21.1@2890,2710
  Signal Layer 2 w15: TP21.1@2890,2710 2980,2620 2980,2489.7 3467.41,2002.29 4375.12,2002.29 4388.9,2016.07 v9(4390.25,2016.07)
EN_3V3_VCCO: R39.2 TP19.1 U6.3 U22.18 | length 6254.4
  Top Layer w10: U22.18@5871.7,6252.29 5945.04,6252.29 5957.33,6240 v1(5957.33,6192.35) ; v7(6560,5806.92) 6634.04,5806.92 U6.3@6634.41,5806.54
  Top Layer w15: 2619.49,2880 2880,2880 TP19.1@2890,2870
  Signal Layer 2 w10: TP19.1@2890,2870 3049.7,2870 4421,4241.3 4421,4564 4419,4566 4419,4888.7 4809.82,5279.52 5044.5,5279.52 v1(5957.33,6192.35) 6063.41,6192.35 6085.76,6170 6502.35,6170 6540,6132.35 6540,5829.34 6560,5809.34 v7(6560,5806.92)
EN_5V0_SYS: R111.2 U17.5 | length 772.4
  Top Layer w20: R111.2@3780,6381.5 v5(3780,6440) ; v5(4300,6260) U17.5@4300,6327.95
  Signal Layer 2 w20: v5(3780,6440) 3810,6470 3916.38,6470 4158.38,6228 4266.95,6228 4298.95,6260 v5(4300,6260)
EN_12V0_SYS: TP23.1 U3.22 U4.3 | length 1075.9
  Top Layer w10: U4.3@2059.75,2825.59 2181.64,2825.59 ; U3.22@2214,2690 2193.56,2690 2190,2693.56 2190,2817.23 2181.64,2825.59 ; TP23.1@2890,3030 2871.03,3030 2831.03,2990 2346.05,2990 2181.64,2825.59
EN_DDR_VTT: R43.2 TP24.1 U16.17 U16.18 U16.19 U16.20 | length 3654.4
  Top Layer w6: U16.20@5774.04,1952.5 U16.20@5775.19,1953.65
  Top Layer w12: v5(5775,1845) 5775,1876.69 U16.17@5775.19,1876.88 U16.20@5775.19,1953.65
  Top Layer w15: R43.2@2621.5,2740 2700,2740 TP24.1@2890,2550
  Signal Layer 2 w15: TP24.1@2890,2550 3618.94,1821.06 5751.06,1821.06 v5(5775,1845)
FAULT_0V8: R10.2 U1.19 | length 283.5
  Top Layer w15: R10.2@2380,3924.39 2380,3790.79 2462.9,3707.89 2493.64,3707.89 U1.19@2495,3706.54
FAULT_SEQ: R53.1 R68.1 TP28.1 U3.7 U5.7 | length 1669.3
  Top Layer w10: R53.1@1601.5,2430 1702.06,2430 1732.5,2460.44 1732.5,2514.99 1750.5,2532.99 1750.5,2534.14 1756.36,2540 U3.7@1808.88,2540
  Top Layer w12: R53.1@1601.5,2430 1601.5,2404.97 1578.27,2381.74 1501.74,2381.74 1370,2250 TP28.1@1370,2240 1370,2081.11 1314.5,2025.61 1314.5,1897.01 1521.51,1690 1580,1690 1603.49,1713.49 R68.1@1603.49,1745.55 1715.46,1745.55 1735.49,1765.58 1735.49,1809.25 1767.26,1841.02 1808.53,1841.02 U5.7@1808.76,1841.24
FB_1V2: C162.2 R121.1 R125.2 U18.11 | length 255
  Top Layer w10: U18.11@5660.87,3067.8 5660.87,3024.94 5686.54,2999.27 5686.54,2998.28 5700.24,2984.58 R121.1@5701.22,2984.58
  Top Layer w25: R121.1@5701.22,2984.58 5702.21,2983.6 5702.21,2831.85 R125.2@5703.19,2830.87
FB_1V2_MEM: C183.2 R131.1 R135.2 U20.11 | length 255
  Top Layer w10: U20.11@5632.23,4116.25 5632.23,4073.39 5657.9,4047.72 5657.9,4046.73 5671.6,4033.03 R131.1@5672.59,4033.03
  Top Layer w25: R131.1@5672.59,4033.03 5673.57,4032.05 5673.57,3880.3 R135.2@5674.56,3879.32
FB_1V2_VCCO: C163.2 R122.1 R126.2 U19.11 | length 255
  Top Layer w10: U19.11@5636.58,5152.7 5636.58,5109.84 5662.25,5084.17 5662.25,5083.18 5675.95,5069.48 R122.1@5676.94,5069.48
  Top Layer w25: R122.1@5676.94,5069.48 5677.92,5068.5 5677.92,4916.75 R126.2@5678.9,4915.77
FB_2V5_DDR: C184.2 R132.1 R136.2 U21.11 | length 255
  Top Layer w10: U21.11@4182.44,2007.91 4182.44,1965.05 4208.11,1939.38 4208.11,1938.39 4221.81,1924.69 R132.1@4222.79,1924.69
  Top Layer w25: R132.1@4222.79,1924.69 4223.78,1923.71 4223.78,1771.96 R136.2@4224.76,1770.98
FB_3V3_VCCO: C195.2 R139.1 R141.2 U22.11 | length 255
  Top Layer w10: U22.11@5728,6212.92 5728,6170.05 5753.67,6144.39 5753.67,6143.4 5767.37,6129.7 R139.1@5768.35,6129.7
  Top Layer w25: R139.1@5768.35,6129.7 5769.34,6128.72 5769.34,5976.97 R141.2@5770.32,5975.98
FB_5V0_SYS: C144.2 R113.1 R114.2 U17.4 | length 330.7
  Top Layer w20: R114.2@4201.5,6210 4250,6210 ; U17.4@4250,6327.95 4250,6210 ; R113.1@4278.5,6210 4250,6210
  Top Layer w25: R114.2@4201.5,6210 4200,6208.5 4200,6170 4240,6130 C144.2@4278.5,6130
FB_PG_0V92: R104.1 R109.2 U15.26 | length 203.5
  Top Layer w10: U15.26@4220.7,3211.01 U15.26@4220,3210.32 4258.76,3210.32 4264.61,3216.17 4264.61,3243.51 4278.89,3257.78 R104.1@4310.32,3257.78
  Top Layer w25: R104.1@4310.32,3257.78 R109.2@4386.82,3257.78
FB_PG_1V5: R86.1 R94.2 U14.26 | length 187.9
  Top Layer w10: U14.26@4184.11,4273.37 4187.96,4277.22 4217.46,4277.22 4239.19,4298.96 4265.19,4298.96 4278.89,4312.66 R86.1@4278.89,4313.03
  Top Layer w25: R86.1@4278.89,4313.03 R94.2@4355.39,4313.03
FB_PG_1V5_GTY: R85.1 R89.2 U13.26 | length 187.9
  Top Layer w10: U13.26@4214.11,5333.37 4217.96,5337.22 4247.46,5337.22 4269.19,5358.96 4295.19,5358.96 4308.89,5372.66 R85.1@4308.89,5373.03
  Top Layer w25: R85.1@4308.89,5373.03 R89.2@4385.39,5373.03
